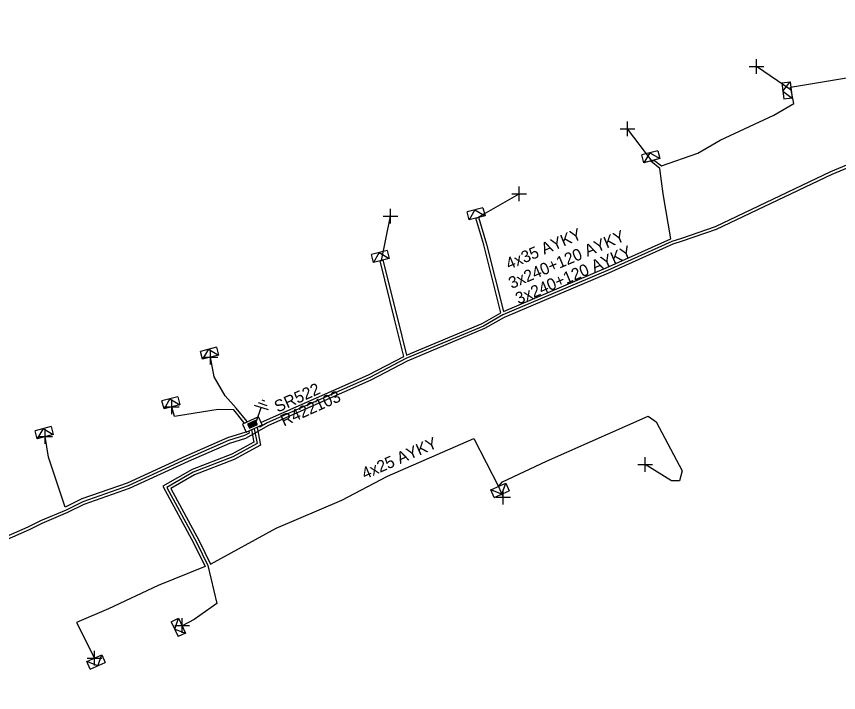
# Model space of a CAD drawing. Extents: x -540466 to -537383, y -1184038 to -1179972.
# Drawn here: x -538781.5 to -538711.4, y -1180487.7 to -1180430.1 of the extents above; entities that cross this region are included whole.
import ezdxf

# ---------------------------------------------------------------- set-up
doc = ezdxf.new("R2010")
doc.units = 0
for name, color, linetype in [('Vrstva 1', 7, 'Continuous'), ('Vrstva 14', 7, 'Continuous'), ('Vrstva 15', 7, 'Continuous'), ('Vrstva 28', 7, 'Continuous'), ('Vrstva 29', 7, 'Continuous'), ('Vrstva 30', 7, 'Continuous'), ('Vrstva 31', 7, 'Continuous'), ('Vrstva 34', 7, 'Continuous'), ('Vrstva 5', 7, 'Continuous'), ('Vrstva 52', 7, 'Continuous'), ('Vrstva 59', 7, 'Continuous'), ('Vrstva 6', 7, 'Continuous'), ('Vrstva 8', 7, 'Continuous'), ('Vrstva 9', 7, 'Continuous')]:
    doc.layers.add(name, color=color, linetype=linetype)

# ---------------------------------------------------------------- blocks, each defined once
blk = doc.blocks.new('NN800')
at = {"layer": 'Vrstva 1'}
for points in [[(-0.442, 0.442), (0.442, -0.442)], [(-0.442, -0.442), (0.442, 0.442)]]:
    blk.add_lwpolyline(points, dxfattribs=at)
blk = doc.blocks.new('NN620')
at = {"layer": 'Vrstva 8'}
for points in [[(0.752, 0.004), (-0.748, 0.004)], [(-0.748, 0.004), (-0.748, -0.746)], [(0.752, -0.746), (0.752, 0.004)], [(0.368, -0.18), (-0.376, -0.18)], [(-0.376, -0.18), (-0.376, -0.558)], [(-0.376, -0.558), (0.368, -0.558)], [(0.321, -0.227), (-0.329, -0.227)], [(-0.329, -0.227), (-0.329, -0.51)], [(-0.329, -0.51), (0.321, -0.51)], [(0.274, -0.274), (-0.281, -0.274)], [(-0.281, -0.274), (-0.281, -0.463)], [(-0.281, -0.463), (0.274, -0.463)], [(0.227, -0.321), (-0.234, -0.321)], [(-0.234, -0.321), (-0.234, -0.416)], [(-0.234, -0.416), (0.227, -0.416)], [(-0.193, -0.369), (0.185, -0.369)], [(0.227, -0.416), (0.227, -0.321)], [(0.274, -0.463), (0.274, -0.274)], [(0.321, -0.51), (0.321, -0.227)], [(0.368, -0.558), (0.368, -0.18)], [(-0.748, -0.746), (0.752, -0.746)]]:
    blk.add_lwpolyline(points, dxfattribs=at)
blk = doc.blocks.new('NN630')
at = {"layer": 'Vrstva 9'}
for points in [[(-0.003, -0.7), (-0.703, 0)], [(-0.703, -0.7), (-0.703, 0), (0.697, 0), (0.697, -0.7)], [(-0.703, -0.7), (0.697, -0.7)], [(-0.003, -0.7), (0.697, 0)]]:
    blk.add_lwpolyline(points, dxfattribs=at)
blk = doc.blocks.new('NN810')
at = {"layer": 'Vrstva 14'}
for points in [[(0.004, -0.64), (0.004, -1.89)], [(0.629, -1.89), (-0.621, -1.89)], [(0.388, -2.2), (-0.399, -2.2)], [(0.004, -2.515), (-0.124, -2.515)], [(0.137, -2.515), (0.004, -2.515)]]:
    blk.add_lwpolyline(points, dxfattribs=at)

msp = doc.modelspace()

# ---------------------------------------------------------------- linework, layer by layer
at = {"layer": 'Vrstva 5'}
for points in [[(-538742.207, -1180447.222), (-538742.071, -1180447.17), (-538741.389, -1180449.467), (-538739.945, -1180455.205), (-538731.19, -1180451.481), (-538725.681, -1180449.017), (-538726.34, -1180445.19), (-538726.608, -1180443.017), (-538727.39, -1180442.397), (-538727.301, -1180442.357), (-538727.078, -1180442.325), (-538726.49, -1180442.791), (-538723.38, -1180441.7), (-538721.49, -1180440.61), (-538716.9, -1180438.48), (-538715.2, -1180437.47), (-538715.426, -1180436.333), (-538715.474, -1180436.087), (-538710.35, -1180435.23), (-538704.62, -1180434.1), (-538701.36, -1180433.63), (-538698.321, -1180432.385), (-538698.903, -1180430.051)], [(-538697.187, -1180434.7), (-538697.736, -1180434.92), (-538697.755, -1180436.679), (-538699.801, -1180437.526), (-538708.662, -1180441.876), (-538712.071, -1180443.306), (-538721.907, -1180447.984), (-538724.772, -1180448.979), (-538725.59, -1180449.25), (-538731.09, -1180451.71), (-538740, -1180455.5), (-538741.67, -1180456.45), (-538748.28, -1180459.23), (-538751.36, -1180460.84), (-538760.103, -1180464.717), (-538760.721, -1180465.061), (-538760.738, -1180464.995)], [(-538708.558, -1180442.104), (-538711.969, -1180443.534), (-538721.813, -1180448.216), (-538724.708, -1180449.221), (-538725.499, -1180449.483), (-538730.99, -1180451.939), (-538739.889, -1180455.724), (-538741.559, -1180456.675), (-538748.173, -1180459.456), (-538751.251, -1180461.065), (-538759.997, -1180464.943), (-538761.955, -1180466.029), (-538763.312, -1180466.454), (-538766.844, -1180467.996), (-538771.856, -1180470.312), (-538775.723, -1180471.661), (-538777.129, -1180472.364), (-538779.304, -1180473.292), (-538780.398, -1180473.844), (-538785.394, -1180476.027)], [(-538760.592, -1180464.659), (-538751.469, -1180460.615), (-538748.455, -1180459.04), (-538749.241, -1180455.87), (-538750.481, -1180450.9), (-538750.367, -1180450.859), (-538750.239, -1180450.84), (-538748.999, -1180455.81), (-538748.225, -1180458.935), (-538741.781, -1180456.225), (-538740.176, -1180455.313), (-538741.631, -1180449.533), (-538742.311, -1180447.242), (-538742.207, -1180447.222)], [(-538760.968, -1180465.098), (-538760.68, -1180466.612), (-538762.915, -1180467.837), (-538766.292, -1180469.136), (-538768.324, -1180470.305), (-538765.897, -1180474.766), (-538764.94, -1180476.759), (-538759.34, -1180473.7), (-538753.73, -1180471.31), (-538749.83, -1180469.25), (-538742.49, -1180466.04), (-538740.379, -1180470.143), (-538740.03, -1180469.75), (-538736.29, -1180467.98), (-538727.61, -1180464.15), (-538726.93, -1180464.62), (-538724.72, -1180468.8), (-538724.95, -1180469.66), (-538725.621, -1180469.647)], [(-538761.671, -1180465.413), (-538761.633, -1180465.583), (-538762.03, -1180465.79), (-538763.4, -1180466.22), (-538766.95, -1180467.77), (-538771.95, -1180470.08), (-538775.82, -1180471.43), (-538777.24, -1180472.14), (-538779.416, -1180473.068), (-538780.502, -1180473.616), (-538785.5, -1180475.8), (-538788.12, -1180477.32), (-538794.33, -1180480.4), (-538799.29, -1180482.44), (-538810.293, -1180487.211), (-538810.912, -1180487.706), (-538811.009, -1180487.457)]]:
    msp.add_lwpolyline(points, dxfattribs=at)
at = {"layer": 'Vrstva 52'}
for points in [[(-538761.821, -1180464.604), (-538762.752, -1180463.442), (-538763.68, -1180462.4), (-538764.63, -1180460.78), (-538764.93, -1180459.11)], [(-538762.057, -1180464.71), (-538762.948, -1180463.598), (-538764.29, -1180463.57), (-538767.67, -1180464.11), (-538768.016, -1180464.168), (-538768.22, -1180463.34)], [(-538761.203, -1180465.204), (-538760.96, -1180466.48), (-538763.02, -1180467.61), (-538766.4, -1180468.91), (-538768.66, -1180470.21), (-538766.12, -1180474.88), (-538765.16, -1180476.88), (-538764.4, -1180480.11), (-538766.32, -1180481.48), (-538767.355, -1180482.002)], [(-538761.917, -1180465.492), (-538763.488, -1180465.986), (-538767.052, -1180467.542), (-538772.044, -1180469.848), (-538775.917, -1180471.199), (-538777.32, -1180471.901), (-538778.75, -1180467.64), (-538779.03, -1180465.88)], [(-538761.438, -1180465.309), (-538761.24, -1180466.348), (-538763.125, -1180467.383), (-538766.508, -1180468.684), (-538768.996, -1180470.115), (-538766.343, -1180474.994), (-538765.397, -1180476.964), (-538769.4, -1180478.57), (-538773.62, -1180480.56), (-538776.36, -1180481.72), (-538774.835, -1180484.78)]]:
    msp.add_lwpolyline(points, dxfattribs=at)
at = {"layer": 'Vrstva 59'}
for points in [[(-538715.426, -1180436.333), (-538718.374, -1180434.321)], [(-538727.301, -1180442.357), (-538729.384, -1180439.633)], [(-538742.207, -1180447.222), (-538738.627, -1180445.176)], [(-538750.367, -1180450.859), (-538749.588, -1180447.077)], [(-538725.621, -1180469.647), (-538727.861, -1180468.269)], [(-538740.379, -1180470.143), (-538739.972, -1180471.056)]]:
    msp.add_lwpolyline(points, dxfattribs=at)

# ---------------------------------------------------------------- block references
at = {"layer": 'Vrstva 15', "rotation": 161.59674161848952}
msp.add_blockref('NN810', (-538761.208, -1180465.179), dxfattribs=at)
at = {"layer": 'Vrstva 28', "rotation": -155.87169444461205}
msp.add_blockref('NN620', (-538761.208, -1180465.179), dxfattribs=at)
at = {"layer": 'Vrstva 31'}
for p, rotation in [((-538715.426, -1180436.333), -82.89493889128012), ((-538727.301, -1180442.357), -165.30830003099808), ((-538742.207, -1180447.222), -165.30830003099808), ((-538750.367, -1180450.859), -165.30829989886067), ((-538764.93, -1180459.11), -165.30830003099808), ((-538768.22, -1180463.34), -165.30830003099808), ((-538779.03, -1180465.88), -165.30830004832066), ((-538740.379, -1180470.143), 24.050313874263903), ((-538767.355, -1180482.002), -64.40696675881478), ((-538774.835, -1180484.78), 24.34337511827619)]:
    msp.add_blockref('NN630', p, dxfattribs=dict(at, rotation=rotation))
at = {"layer": 'Vrstva 34'}
for p, rotation in [((-538718.374, -1180434.321), 44.99999995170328), ((-538729.384, -1180439.633), 45), ((-538738.627, -1180445.176), 45), ((-538749.588, -1180447.077), 45), ((-538764.93, -1180459.11), 45), ((-538768.22, -1180463.34), 45), ((-538779.03, -1180465.88), 45), ((-538727.861, -1180468.269), 45), ((-538739.972, -1180471.056), 44.99999995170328), ((-538767.355, -1180482.001), 45), ((-538774.835, -1180484.78), 45)]:
    msp.add_blockref('NN800', p, dxfattribs=dict(at, rotation=rotation))

# ---------------------------------------------------------------- texts
at = {"layer": 'Vrstva 29'}
msp.add_text('R422103', height=1, rotation=24.128, dxfattribs=at).set_placement((-538758.683, -1180465.032))
at = {"layer": 'Vrstva 30'}
msp.add_text('SR522', height=1, rotation=24.128, dxfattribs=at).set_placement((-538759.215, -1180463.845))
at = {"layer": 'Vrstva 6'}
for s, rotation, p in [('4x35 AYKY', 23.043, (-538739.491, -1180451.661)), ('3x240+120 AYKY', 23.043, (-538739.26, -1180453.296)), ('3x240+120 AYKY', 23.041, (-538738.676, -1180454.617)), ('4x25 AYKY', 23.621, (-538751.777, -1180469.539))]:
    msp.add_text(s, height=1, rotation=rotation, dxfattribs=at).set_placement(p)

doc.saveas('drawing.dxf')
